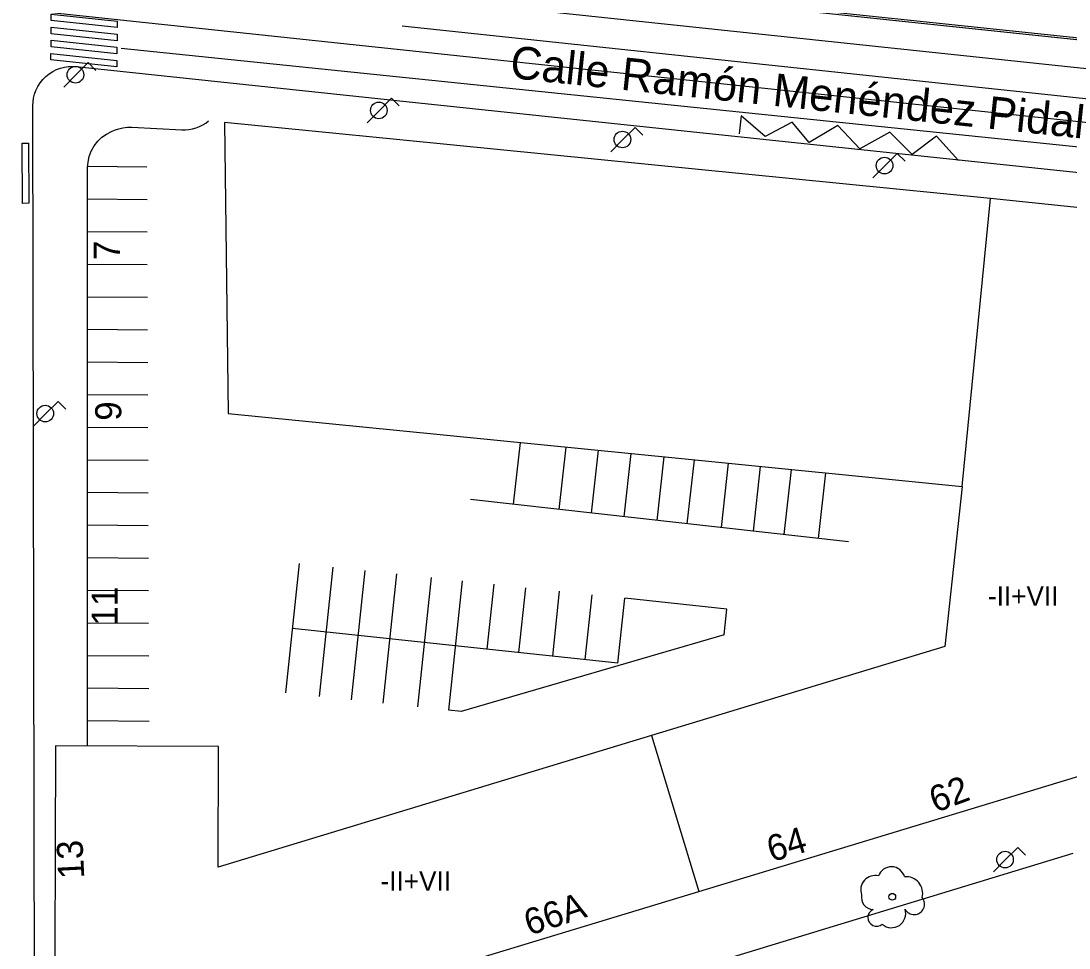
# Model space of a CAD drawing. Extents: x 282771 to 285132, y 4823109 to 4825496.
# Drawn here: x 282862 to 282942.4, y 4823958.4 to 4824029.5 of the extents above; entities that cross this region are included whole.
import ezdxf

# ---------------------------------------------------------------- set-up
doc = ezdxf.new("R2010")
doc.units = 0
for name, color, linetype in [('ACERA-BORDILLO', 7, 'Continuous'), ('ACERA-INTERIOR', 7, 'Continuous'), ('APARCAMIENTO', 7, 'Continuous'), ('ARBOL', 7, 'Continuous'), ('BORDILLO', 7, 'Continuous'), ('CALLE-EJE', 7, 'Continuous'), ('CALLE-TEXTO', 7, 'Continuous'), ('CARGA_DESCARGA', 7, 'Continuous'), ('EDIFICIO', 7, 'Continuous'), ('FAROLA', 7, 'Continuous'), ('MEDIANERA', 7, 'Continuous'), ('NUM-PORTAL', 7, 'Continuous'), ('PARQUE-JARDIN-AREA', 7, 'Continuous'), ('PASO-PEATONES', 7, 'Continuous'), ('SENAL-VIARIA', 7, 'Continuous'), ('TXT-ALTURA-EDIFICIO', 7, 'Continuous'), ('ZONA-VERDE', 7, 'Continuous')]:
    doc.layers.add(name, color=color, linetype=linetype)

msp = doc.modelspace()

# ---------------------------------------------------------------- linework, layer by layer
at = {"layer": 'ACERA-BORDILLO'}
for points in [[(282988.023, 4824157.68), (282986.043, 4824139.146), (282981.145, 4824135.33), (282970.859, 4824041.966), (282974.673, 4824036.985), (282973.917, 4824027.481), (282973.629, 4824024.412), (282973.445, 4824023.861), (282973.196, 4824023.428), (282972.724, 4824023.074), (282972.2, 4824022.851), (282971.518, 4824022.891), (282891.09, 4824031.424)], [(282863.088, 4823941.606), (282862.944, 4824023.007), (282862.957, 4824023.291), (282862.999, 4824023.584), (282863.073, 4824023.881), (282863.179, 4824024.176), (282863.32, 4824024.466), (282863.494, 4824024.744), (282863.7, 4824025.004), (282863.935, 4824025.241), (282864.195, 4824025.45), (282864.475, 4824025.628), (282864.77, 4824025.773), (282865.072, 4824025.883), (282865.377, 4824025.958), (282865.68, 4824026.001), (282865.975, 4824026.012), (282866.259, 4824025.996), (282891.09, 4824023.374), (283009.796, 4824010.845)], [(282942.7, 4823965.654), (282891.09, 4823949.934)]]:
    msp.add_lwpolyline(points, dxfattribs=at)
at = {"layer": 'ACERA-INTERIOR'}
msp.add_lwpolyline([(282867.144, 4823973.896), (282867.144, 4824018.254), (282867.174, 4824018.676), (282867.266, 4824019.102), (282867.424, 4824019.52), (282867.645, 4824019.913), (282867.922, 4824020.269), (282868.245, 4824020.577), (282868.602, 4824020.828), (282868.979, 4824021.019), (282869.212, 4824021.117), (282869.528, 4824021.229), (282869.856, 4824021.307), (282870.191, 4824021.346), (282870.527, 4824021.348), (282874.369, 4824021.156), (282874.641, 4824021.155), (282874.915, 4824021.179), (282875.188, 4824021.228), (282875.457, 4824021.303), (282875.718, 4824021.402), (282875.967, 4824021.525), (282876.202, 4824021.669), (282876.419, 4824021.831)], dxfattribs=at)
at = {"layer": 'APARCAMIENTO'}
for points in [[(282867.144, 4824018.356), (282871.695, 4824018.319)], [(282867.144, 4824015.856), (282871.705, 4824015.819)], [(282867.144, 4824013.356), (282871.714, 4824013.319)], [(282867.144, 4824010.856), (282871.723, 4824010.818)], [(282867.144, 4824008.356), (282871.732, 4824008.318)], [(282867.144, 4824005.855), (282871.741, 4824005.818)], [(282867.144, 4824003.355), (282871.751, 4824003.318)], [(282867.144, 4824000.855), (282871.76, 4824000.818)], [(282867.144, 4823998.355), (282871.769, 4823998.318)], [(282900.307, 4823997.171), (282899.776, 4823992.435)], [(282903.804, 4823996.824), (282903.268, 4823992.044)], [(282906.287, 4823996.578), (282905.747, 4823991.766)], [(282908.806, 4823996.328), (282908.263, 4823991.484)], [(282911.325, 4823996.078), (282910.779, 4823991.202)], [(282867.144, 4823995.855), (282871.778, 4823995.818)], [(282913.645, 4823995.848), (282913.095, 4823990.942)], [(282916.271, 4823995.588), (282915.717, 4823990.648)], [(282918.724, 4823995.344), (282918.167, 4823990.374)], [(282921.094, 4823995.109), (282920.534, 4823990.109)], [(282923.73, 4823994.848), (282923.166, 4823989.814)], [(282867.144, 4823993.355), (282871.788, 4823993.318)], [(282925.495, 4823989.553), (282896.499, 4823992.802)], [(282867.144, 4823990.855), (282871.797, 4823990.817)], [(282867.144, 4823988.355), (282871.806, 4823988.317)], [(282882.332, 4823977.986), (282883.384, 4823987.888)], [(282884.932, 4823977.709), (282885.984, 4823987.612)], [(282887.383, 4823977.449), (282888.435, 4823987.352)], [(282889.8, 4823977.192), (282890.852, 4823987.095)], [(282892.456, 4823976.91), (282893.508, 4823986.813)], [(282894.84, 4823976.657), (282895.892, 4823986.559)], [(282897.777, 4823981.323), (282898.306, 4823986.303)], [(282867.144, 4823985.855), (282871.815, 4823985.817)], [(282900.222, 4823981.063), (282900.751, 4823986.043)], [(282902.804, 4823980.789), (282903.333, 4823985.769)], [(282905.295, 4823980.525), (282905.824, 4823985.505)], [(282907.803, 4823980.258), (282908.332, 4823985.238)], [(282916.167, 4823984.406), (282908.332, 4823985.238)], [(282915.955, 4823982.418), (282916.167, 4823984.406)], [(282867.144, 4823983.355), (282871.825, 4823983.317)], [(282907.803, 4823980.258), (282882.855, 4823982.908)], [(282915.955, 4823982.418), (282895.779, 4823976.557)], [(282867.144, 4823980.855), (282871.834, 4823980.817)], [(282867.144, 4823978.355), (282871.843, 4823978.317)], [(282895.779, 4823976.557), (282894.84, 4823976.657)], [(282867.144, 4823975.855), (282871.852, 4823975.817)]]:
    msp.add_lwpolyline(points, dxfattribs=at)
at = {"layer": 'ARBOL'}
msp.add_circle((282928.848, 4823962.347), 0.255, dxfattribs=at)
for centre, radius, start, end in [((282928.778, 4823963.607), 1.038, 15.64228, 161.38435), ((282927.518, 4823962.877), 1.097, 75.4318, 200.55608), ((282929.908, 4823962.607), 1.272, 345.03273, 95.79925), ((282927.408, 4823962.307), 0.935, 168.59898, 268.13236), ((282930.518, 4823961.777), 0.797, 208.96247, 38.99103), ((282927.648, 4823960.757), 0.672, 113.73672, 309.4725), ((282928.788, 4823961.057), 1.086, 228.95447, 17.92796)]:
    msp.add_arc(centre, radius, start, end, dxfattribs=at)
at = {"layer": 'BORDILLO'}
msp.add_lwpolyline([(282900.447, 4824032.562), (282957.582, 4824026.536), (282958.046, 4824026.762), (282958.502, 4824027.028), (282958.945, 4824027.333), (282959.369, 4824027.677), (282959.77, 4824028.058), (282960.143, 4824028.473), (282960.484, 4824028.919), (282960.789, 4824029.393), (282961.055, 4824029.89)], dxfattribs=at)
at = {"layer": 'CALLE-EJE'}
msp.add_lwpolyline([(282977.366, 4824018.14), (282859.299, 4824030.65)], dxfattribs=at)
at = {"layer": 'CARGA_DESCARGA'}
msp.add_lwpolyline([(282933.917, 4824018.799), (282932.248, 4824020.672), (282930.376, 4824019.247), (282928.666, 4824020.957), (282926.346, 4824019.695), (282924.677, 4824021.487), (282922.479, 4824020.183), (282921.176, 4824021.731), (282919.101, 4824020.631), (282917.269, 4824022.22), (282917.106, 4824020.835)], dxfattribs=at)
at = {"layer": 'EDIFICIO'}
msp.add_lwpolyline([(282932.884, 4823981.535), (282910.372, 4823974.705), (282877.151, 4823964.625), (282877.186, 4823973.858), (282864.686, 4823973.906), (282864.597, 4823950.251), (282866.98, 4823948.476), (282914.001, 4823962.743), (282944.335, 4823971.947), (282948.9, 4824014.584), (282936.387, 4824015.883), (282891.09, 4824020.375), (282877.649, 4824021.709), (282877.924, 4823999.391), (282891.09, 4823998.085), (282912.455, 4823995.966), (282934.198, 4823993.81), (282932.884, 4823981.535)], dxfattribs=at)
at = {"layer": 'FAROLA'}
for p, q in [((282867.192, 4824026.299), (282866.252, 4824025.37)), ((282867.782, 4824025.71), (282867.192, 4824026.299)), ((282866.252, 4824025.37), (282865.322, 4824024.43)), ((282890.455, 4824023.567), (282889.515, 4824022.637)), ((282891.045, 4824022.977), (282890.455, 4824023.567)), ((282889.515, 4824022.637), (282888.585, 4824021.697)), ((282909.129, 4824021.338), (282908.189, 4824020.408)), ((282909.719, 4824020.748), (282909.129, 4824021.338)), ((282908.189, 4824020.408), (282907.259, 4824019.468)), ((282929.231, 4824019.336), (282928.291, 4824018.406)), ((282929.821, 4824018.746), (282929.231, 4824019.336)), ((282928.291, 4824018.406), (282927.361, 4824017.466)), ((282864.879, 4824000.324), (282863.939, 4823999.394)), ((282865.469, 4823999.734), (282864.879, 4824000.324)), ((282863.939, 4823999.394), (282863.009, 4823998.454)), ((282938.47, 4823966.124), (282937.53, 4823965.194)), ((282939.06, 4823965.534), (282938.47, 4823966.124)), ((282937.53, 4823965.194), (282936.6, 4823964.254))]:
    msp.add_line(p, q, dxfattribs=at)
for centre in [(282866.212, 4824025.37), (282889.475, 4824022.637), (282908.149, 4824020.408), (282928.251, 4824018.406), (282863.899, 4823999.394), (282937.49, 4823965.194)]:
    msp.add_circle(centre, 0.637, dxfattribs=at)
at = {"layer": 'MEDIANERA'}
for points in [[(282934.198, 4823993.81), (282936.387, 4824015.883)], [(282910.372, 4823974.705), (282914.001, 4823962.743)]]:
    msp.add_lwpolyline(points, dxfattribs=at)
at = {"layer": 'PARQUE-JARDIN-AREA'}
msp.add_lwpolyline([(282967.734, 4824033.817), (282959.864, 4824028.159), (282959.7, 4824027.988), (282959.53, 4824027.823), (282959.355, 4824027.664), (282959.174, 4824027.51), (282958.988, 4824027.363), (282958.798, 4824027.223), (282958.603, 4824027.088), (282958.403, 4824026.961), (282958.199, 4824026.84), (282957.991, 4824026.726), (282957.78, 4824026.62), (282957.565, 4824026.52), (282900.429, 4824032.546)], dxfattribs=at)
at = {"layer": 'PASO-PEATONES'}
for points in [[(282869.4, 4824028.99), (282864.342, 4824029.524), (282864.343, 4824030.027), (282869.401, 4824029.493)], [(282869.398, 4824027.985), (282864.339, 4824028.519), (282864.34, 4824029.022), (282869.399, 4824028.488)], [(282869.395, 4824026.98), (282864.337, 4824027.514), (282864.338, 4824028.016), (282869.397, 4824027.482)], [(282869.393, 4824025.974), (282864.334, 4824026.509), (282864.336, 4824027.011), (282869.394, 4824026.477)], [(282862.14, 4824015.512), (282862.116, 4824020.125), (282862.616, 4824020.127), (282862.64, 4824015.515)]]:
    msp.add_lwpolyline(points, close=True, dxfattribs=at)
at = {"layer": 'SENAL-VIARIA'}
for points in [[(282891.276, 4824029.133), (282966.258, 4824021.157)], [(282869.72, 4824027.406), (282950.845, 4824019.041)]]:
    msp.add_lwpolyline(points, dxfattribs=at)
at = {"layer": 'ZONA-VERDE'}
msp.add_lwpolyline([(282900.487, 4824032.709), (282957.555, 4824026.69)], dxfattribs=at)

# ---------------------------------------------------------------- texts
at = {"layer": 'CALLE-TEXTO'}
msp.add_text('Calle Ramón Menéndez Pidal', height=2.5, rotation=353.95188, dxfattribs=at).set_placement((282899.466, 4824025.137))
at = {"layer": 'NUM-PORTAL'}
for s, rotation, p in [('7', 90, (282869.62, 4824011.17)), ('9', 90, (282869.726, 4823998.843)), ('11', 90, (282869.447, 4823983.139)), ('62', 20.48752, (282932.152, 4823968.767)), ('64', 16.89219, (282919.595, 4823964.985)), ('13', 92.8955, (282866.895, 4823963.766)), ('66A', 18.0891, (282901.01, 4823959.351))]:
    msp.add_text(s, height=2, rotation=rotation, dxfattribs=at).set_placement(p)
at = {"layer": 'TXT-ALTURA-EDIFICIO'}
for p in [(282936.182, 4823984.653), (282889.607, 4823962.801)]:
    msp.add_text('-II+VII', height=1.5, rotation=0.00004, dxfattribs=at).set_placement(p)

doc.saveas('drawing.dxf')
